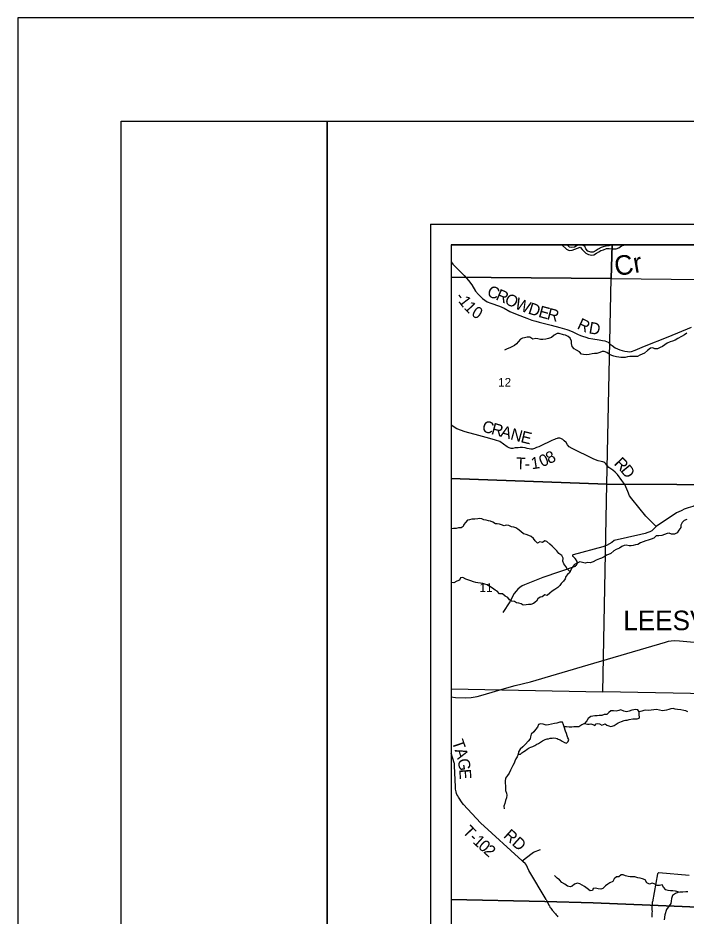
# Model space of a CAD drawing. Extents: x -7.1 to 34, y 0 to 22.
# Drawn here: x 0 to 3.24, y 17.646 to 22 of the extents above; entities that cross this region are included whole.
import ezdxf

# ---------------------------------------------------------------- set-up
doc = ezdxf.new("R2010")
doc.units = 0
for name, color, linetype in [('Default', 7, 'Continuous'), ('GM_X_Corporation_Text', 7, 'Continuous'), ('GM_X_County_Road', 7, 'Continuous'), ('GM_X_Major_River', 7, 'Continuous'), ('GM_X_Major_River_Text', 7, 'Continuous'), ('GM_X_Minor_Lake', 7, 'Continuous'), ('GM_X_Minor_River', 7, 'Continuous'), ('GM_X_Section', 7, 'Continuous'), ('GM_X_Section_Text', 7, 'Continuous'), ('GM_X_Township_Road', 7, 'Continuous'), ('GM_X_Township_Road_Text', 7, 'Continuous'), ('SH_Border', 7, 'Continuous'), ('SH_Cut_Line', 7, 'Continuous'), ('SH_Data', 7, 'Continuous')]:
    doc.layers.add(name, color=color, linetype=linetype)

msp = doc.modelspace()

# ---------------------------------------------------------------- linework, layer by layer
at = {"layer": 'Default'}
for points in [[(2.8816, 20.9), (2.1, 20.9), (2.1, 20.744), (2.8771, 20.7376)], [(3.8966, 20.9), (2.8816, 20.9), (2.8771, 20.7376), (3.8931, 20.7247), (3.8945, 20.8149)], [(2.1, 20.744), (2.1, 19.7672), (2.8549, 19.7393), (2.8771, 20.7376)], [(2.1, 19.7672), (2.1, 18.7473), (2.8366, 18.7324), (2.8549, 19.7393)]]:
    msp.add_lwpolyline(points, close=True, dxfattribs=at)
at = {"layer": 'GM_X_County_Road'}
for points in [[(2.1, 18.7082), (2.1223, 18.7056), (2.1681, 18.7043), (2.1971, 18.7058), (2.2265, 18.7097), (2.2451, 18.7146), (2.2989, 18.7315), (2.3593, 18.7497), (2.4106, 18.7642), (2.485, 18.7817), (2.7659, 18.8631), (3.1394, 18.9737), (3.1551, 18.9777), (3.1669, 18.9796), (3.1823, 18.9814), (3.2073, 18.9808), (3.3146, 18.9707)], [(2.5617, 17.7254), (2.5679, 17.7128), (2.5748, 17.6987), (2.577, 17.6944), (2.5799, 17.6895), (2.5834, 17.6843), (2.5874, 17.6787), (2.5909, 17.6743), (2.606, 17.6566), (2.6103, 17.6518), (2.6154, 17.6461), (2.6188, 17.6425)]]:
    msp.add_lwpolyline(points, dxfattribs=at)
at = {"layer": 'GM_X_Major_River'}
for points in [[(2.6372, 20.9), (2.6597, 20.8783), (2.6734, 20.8725), (2.6875, 20.8735), (2.6999, 20.8797), (2.7139, 20.8845), (2.7264, 20.8893), (2.7357, 20.8773), (2.745, 20.8672), (2.7546, 20.859), (2.7669, 20.8539), (2.7825, 20.8496), (2.7924, 20.8517), (2.8055, 20.8599), (2.8165, 20.8658), (2.8262, 20.8727), (2.8391, 20.8764), (2.8535, 20.8819), (2.8668, 20.8818), (2.8782, 20.8804), (2.8877, 20.8802), (2.9006, 20.8812), (2.9135, 20.8856), (2.927, 20.8949), (2.9383, 20.8981), (2.9491, 20.9)], [(2.8887, 20.9), (2.8771, 20.8979), (2.8646, 20.895), (2.8521, 20.8929), (2.8385, 20.89), (2.8287, 20.8872), (2.8132, 20.8797), (2.8034, 20.8724), (2.7899, 20.8645), (2.7774, 20.864), (2.7643, 20.8694), (2.7543, 20.8806), (2.7487, 20.8934), (2.7361, 20.8989), (2.7243, 20.8987), (2.7118, 20.8962), (2.699, 20.8888), (2.6861, 20.8871), (2.6739, 20.8884), (2.6627, 20.9)]]:
    msp.add_lwpolyline(points, dxfattribs=at)
at = {"layer": 'GM_X_Minor_Lake'}
for points in [[(3.012, 18.635), (3.0062, 18.6448), (2.9967, 18.647), (2.9865, 18.6454), (2.9766, 18.6434), (2.9645, 18.6387), (2.9505, 18.6352), (2.9375, 18.6393), (2.9238, 18.6456), (2.9139, 18.6428), (2.9007, 18.6397), (2.8881, 18.64), (2.8752, 18.6406), (2.8654, 18.6333), (2.8556, 18.623), (2.8423, 18.6221), (2.8317, 18.6186), (2.8188, 18.6177), (2.8086, 18.6161), (2.7979, 18.6157), (2.7884, 18.6148), (2.7782, 18.6132), (2.7654, 18.6032), (2.7594, 18.5914), (2.7477, 18.5799)], [(2.7477, 18.5799), (2.7614, 18.5755), (2.7698, 18.5767), (2.7785, 18.5779), (2.7876, 18.5749), (2.7968, 18.5697), (2.804, 18.5774), (2.8115, 18.5797), (2.8203, 18.5779), (2.831, 18.5719), (2.8393, 18.575), (2.8476, 18.577), (2.856, 18.5714), (2.8648, 18.5673), (2.8736, 18.5654), (2.8819, 18.5666), (2.8918, 18.5701), (2.9001, 18.5755), (2.9099, 18.5817), (2.919, 18.5863), (2.9269, 18.5894), (2.9394, 18.5945), (2.9455, 18.5957), (2.955, 18.5961), (2.9644, 18.5985), (2.9811, 18.6017), (2.9929, 18.6018), (3.0032, 18.6026), (3.0122, 18.6046), (3.0141, 18.6103), (3.0125, 18.6209), (3.012, 18.635)], [(2.6491, 18.5631), (2.646, 18.5733), (2.6413, 18.5858), (2.628, 18.585), (2.6133, 18.5803), (2.6011, 18.5794), (2.5875, 18.5759), (2.5731, 18.5735), (2.5617, 18.5715), (2.5465, 18.5755), (2.5347, 18.5769), (2.5244, 18.5746), (2.5188, 18.5612), (2.5094, 18.5505), (2.502, 18.5383), (2.4895, 18.528), (2.4847, 18.5142), (2.4832, 18.5044), (2.4742, 18.4933), (2.461, 18.4795), (2.4482, 18.4669), (2.4354, 18.4546), (2.4272, 18.4416), (2.4261, 18.4298)], [(2.4261, 18.4298), (2.4364, 18.4299), (2.4439, 18.4368), (2.453, 18.4434), (2.4617, 18.4484), (2.47, 18.4541), (2.4791, 18.4607), (2.4874, 18.4645), (2.4969, 18.4677), (2.5063, 18.4719), (2.5161, 18.4785), (2.5244, 18.4827), (2.5343, 18.4885), (2.5441, 18.4954), (2.5566, 18.5012), (2.5664, 18.5043), (2.5721, 18.5051), (2.5812, 18.5075), (2.5911, 18.5087), (2.5994, 18.5092), (2.6086, 18.5077), (2.6143, 18.5066), (2.6204, 18.504), (2.6288, 18.5003), (2.6398, 18.4939), (2.6501, 18.4872), (2.6604, 18.4846), (2.6679, 18.4923), (2.6709, 18.5011), (2.667, 18.5105), (2.6632, 18.5196), (2.6593, 18.5302), (2.6554, 18.5415), (2.6491, 18.5631)]]:
    msp.add_lwpolyline(points, dxfattribs=at)
at = {"layer": 'GM_X_Minor_River'}
for points in [[(3.2428, 20.4712), (3.2319, 20.4639), (3.2175, 20.4558), (3.2005, 20.4461), (3.1877, 20.4384), (3.1733, 20.4326), (3.1623, 20.4299), (3.1487, 20.4225), (3.1373, 20.4149), (3.1249, 20.4068), (3.115, 20.4025), (3.1018, 20.396), (3.0881, 20.3955), (3.0786, 20.4014), (3.0668, 20.3995), (3.0525, 20.3876), (3.0382, 20.3749), (3.0276, 20.3703), (3.0162, 20.3645), (3.0041, 20.3591), (2.9897, 20.3582), (2.9802, 20.3589), (2.9677, 20.358), (2.9552, 20.3568), (2.9438, 20.3544), (2.9328, 20.3531), (2.9233, 20.3534), (2.9138, 20.3549), (2.9027, 20.3571), (2.8898, 20.36), (2.8795, 20.3629), (2.8662, 20.3704), (2.8551, 20.3783), (2.8433, 20.3835), (2.833, 20.3826), (2.8224, 20.3772), (2.8065, 20.3725), (2.7951, 20.3732), (2.7852, 20.3723), (2.7701, 20.3684), (2.7568, 20.3675), (2.7427, 20.3689), (2.7332, 20.3704), (2.7225, 20.3817), (2.7091, 20.3891), (2.698, 20.3962), (2.6869, 20.4075), (2.6838, 20.4223), (2.6848, 20.4333), (2.6778, 20.4469), (2.6679, 20.4555), (2.6545, 20.4623), (2.645, 20.4629), (2.6252, 20.4696), (2.615, 20.4699), (2.5995, 20.4622), (2.5867, 20.4507), (2.5726, 20.4452), (2.5598, 20.4421), (2.5453, 20.4412), (2.5332, 20.4407), (2.5206, 20.444), (2.5111, 20.4455), (2.4963, 20.4431), (2.4826, 20.452), (2.4696, 20.4523), (2.4564, 20.4488)], [(2.4564, 20.4488), (2.4469, 20.4479), (2.4371, 20.4429), (2.425, 20.4299), (2.4183, 20.42), (2.4081, 20.4119), (2.3983, 20.4069), (2.3854, 20.4011), (2.3725, 20.3964), (2.3601, 20.3891)], [(2.6777, 19.3143), (2.663, 19.3295), (2.6565, 19.3408), (2.6469, 19.354), (2.6429, 19.3669), (2.6436, 19.3802), (2.6374, 19.3938), (2.6232, 19.4039), (2.6129, 19.416), (2.5999, 19.4291), (2.5899, 19.4397), (2.5788, 19.4494), (2.5654, 19.4611), (2.5555, 19.4655), (2.5442, 19.4575), (2.5312, 19.46), (2.5195, 19.4535), (2.5088, 19.4651), (2.5007, 19.4764), (2.4884, 19.4858), (2.477, 19.491), (2.4637, 19.4959), (2.4519, 19.4992), (2.4392, 19.5097), (2.4247, 19.5213), (2.4148, 19.5284), (2.4052, 19.5318), (2.3931, 19.5332), (2.3805, 19.5395), (2.3679, 19.5406), (2.3573, 19.5374), (2.3444, 19.5426), (2.3345, 19.5452), (2.3246, 19.5474), (2.3151, 19.5481), (2.3021, 19.5555), (2.2914, 19.5608), (2.2815, 19.5618), (2.2697, 19.5647), (2.2598, 19.5669), (2.2488, 19.571), (2.2389, 19.5724), (2.2294, 19.5712), (2.215, 19.57), (2.2009, 19.5695), (2.1899, 19.5675), (2.1801, 19.5651), (2.1703, 19.5544), (2.1628, 19.5445), (2.1587, 19.5346), (2.1485, 19.5276), (2.1371, 19.5272), (2.1242, 19.5244), (2.1121, 19.5251), (2.1, 19.5223)], [(3.244, 19.5682), (3.2311, 19.5636), (3.2205, 19.554), (3.2142, 19.5411), (3.2139, 19.5289), (3.2049, 19.5171), (3.1959, 19.5033), (3.1834, 19.4979), (3.1698, 19.4974), (3.1579, 19.5015), (3.1485, 19.4999), (3.1356, 19.4952), (3.1227, 19.4902), (3.1079, 19.4885), (3.0946, 19.4884), (3.0833, 19.4781), (3.0708, 19.4727), (3.0561, 19.4687), (3.0443, 19.4648), (3.0326, 19.4598), (3.0193, 19.4551), (3.0053, 19.4474), (2.9944, 19.4451), (2.9841, 19.4419), (2.9739, 19.4407), (2.9632, 19.441), (2.9499, 19.4432), (2.9389, 19.4415), (2.9276, 19.4376), (2.9166, 19.4296), (2.9015, 19.4234), (2.889, 19.4164), (2.8754, 19.4042), (2.8637, 19.3988), (2.8539, 19.3957), (2.8422, 19.388), (2.8293, 19.3806)], [(2.8293, 19.3806), (2.8195, 19.3771), (2.8032, 19.3713), (2.7892, 19.3625), (2.7741, 19.3582), (2.7619, 19.3603), (2.7498, 19.3568), (2.7383, 19.3601), (2.7246, 19.3623), (2.7122, 19.3572), (2.6985, 19.3495), (2.688, 19.335), (2.6802, 19.3209), (2.6765, 19.311), (2.6648, 19.3014), (2.6565, 19.2919), (2.6532, 19.2801), (2.6461, 19.2686), (2.6344, 19.2587), (2.6284, 19.2484), (2.6175, 19.238), (2.6039, 19.2292), (2.5907, 19.2204), (2.579, 19.2111), (2.5669, 19.2004), (2.5543, 19.2037), (2.5419, 19.1926), (2.532, 19.1925), (2.5215, 19.1829), (2.514, 19.173), (2.5004, 19.1615), (2.4871, 19.1568), (2.4765, 19.1556), (2.464, 19.154), (2.4503, 19.1527), (2.4408, 19.1595), (2.4294, 19.1632), (2.4172, 19.165), (2.4073, 19.1702), (2.3939, 19.1731), (2.3844, 19.1795), (2.3752, 19.1896), (2.3626, 19.196), (2.35, 19.2073), (2.3359, 19.2087), (2.3244, 19.2203), (2.3137, 19.2252), (2.3011, 19.2357), (2.2878, 19.2428), (2.2751, 19.2514), (2.2645, 19.2551), (2.2549, 19.2584), (2.2428, 19.2602), (2.2298, 19.262), (2.2196, 19.2634), (2.2085, 19.2664), (2.196, 19.2716), (2.1857, 19.2745), (2.1716, 19.2793), (2.1578, 19.2876), (2.1465, 19.2852), (2.1405, 19.2734), (2.1276, 19.2695), (2.1136, 19.2606), (2.1007, 19.2624), (2.1, 19.2627)], [(3.2479, 18.6355), (3.2383, 18.6403), (3.2284, 18.6425), (3.214, 18.6447), (3.1988, 18.6476), (3.187, 18.6494), (3.1771, 18.6516), (3.1664, 18.6499), (3.1566, 18.6476), (3.1448, 18.6441), (3.1354, 18.6421), (3.1251, 18.6412), (3.1114, 18.6442), (3.0966, 18.6471), (3.0833, 18.6462), (3.07, 18.6442), (3.0571, 18.6429), (3.045, 18.644), (3.0351, 18.6416), (3.0253, 18.6385), (3.012, 18.635), (3.0062, 18.6448), (2.9967, 18.647), (2.9865, 18.6454), (2.9766, 18.6434), (2.9645, 18.6387), (2.9505, 18.6352), (2.9375, 18.6393), (2.9238, 18.6456), (2.9139, 18.6428), (2.9007, 18.6397), (2.8881, 18.64), (2.8752, 18.6406), (2.8654, 18.6333), (2.8556, 18.623), (2.8423, 18.6221), (2.8317, 18.6186), (2.8188, 18.6177), (2.8086, 18.6161), (2.7979, 18.6157), (2.7884, 18.6148), (2.7782, 18.6132), (2.7654, 18.6032), (2.7594, 18.5914), (2.7477, 18.5799), (2.7349, 18.5722), (2.7194, 18.5633), (2.6962, 18.5631), (2.6867, 18.5608), (2.6734, 18.5607), (2.6605, 18.5632), (2.6491, 18.5631), (2.646, 18.5733), (2.6413, 18.5858), (2.628, 18.585), (2.6133, 18.5803), (2.6011, 18.5794), (2.5875, 18.5759), (2.5731, 18.5735), (2.5617, 18.5715), (2.5465, 18.5755), (2.5347, 18.5769), (2.5244, 18.5746), (2.5188, 18.5612), (2.5094, 18.5505), (2.502, 18.5383), (2.4895, 18.528), (2.4847, 18.5142), (2.4832, 18.5044), (2.4742, 18.4933), (2.461, 18.4795), (2.4482, 18.4669), (2.4354, 18.4546), (2.4272, 18.4416), (2.4261, 18.4298), (2.4202, 18.4169), (2.4146, 18.4073), (2.4101, 18.397), (2.406, 18.3875), (2.3992, 18.3761), (2.3952, 18.3658), (2.388, 18.3524), (2.3817, 18.3391), (2.3734, 18.3276), (2.3644, 18.3139), (2.3623, 18.2998), (2.3624, 18.2899), (2.364, 18.2771), (2.3648, 18.266), (2.3649, 18.255), (2.3685, 18.2418), (2.3704, 18.2319), (2.369, 18.219), (2.3646, 18.2064), (2.3617, 18.1912)], [(2.3617, 18.1912), (2.3568, 18.1783), (2.3581, 18.1661)], [(3.2059, 17.7611), (3.1883, 17.7663), (3.1758, 17.7673), (3.1648, 17.7684), (3.1526, 17.7698), (3.1423, 17.7727), (3.1312, 17.7859), (3.1239, 17.7969), (3.1114, 17.7945), (3.0996, 17.794), (3.0858, 17.8019), (3.0759, 17.8044), (3.0623, 17.8001), (3.049, 17.8072), (3.0409, 17.8208), (3.0283, 17.8264), (3.0169, 17.8294), (3.0055, 17.8312), (2.9917, 17.8363), (2.9686, 17.8361), (2.9583, 17.8376), (2.9457, 17.8413), (2.9354, 17.8457), (2.9259, 17.846), (2.9135, 17.8364), (2.9032, 17.8356), (2.8912, 17.8267), (2.8844, 17.8138), (2.8704, 17.8061), (2.8599, 17.8007), (2.8485, 17.7918), (2.8365, 17.7788), (2.827, 17.7768), (2.8129, 17.7782), (2.8, 17.7808), (2.7886, 17.7795), (2.786, 17.7689), (2.7743, 17.768), (2.7601, 17.7789), (2.7468, 17.7883), (2.7368, 17.7954), (2.725, 17.8021), (2.7128, 17.8054), (2.6988, 17.8), (2.6883, 17.7908), (2.6784, 17.7869), (2.6647, 17.7898), (2.6517, 17.7996), (2.6372, 17.8078), (2.6253, 17.8214), (2.615, 17.8297), (2.6012, 17.8421)], [(3.2487, 17.763), (3.2389, 17.7626), (3.2241, 17.7621), (3.2115, 17.7619), (3.2001, 17.7603), (3.1892, 17.7553), (3.1748, 17.7449), (3.1696, 17.7308), (3.1682, 17.7179), (3.1664, 17.7061), (3.1583, 17.6945)], [(3.1583, 17.6945), (3.145, 17.677), (3.1367, 17.6509), (3.1335, 17.627)]]:
    msp.add_lwpolyline(points, dxfattribs=at)
at = {"layer": 'GM_X_Section'}
for points in [[(3.8931, 20.7247), (3.8731, 19.8315), (3.8749, 19.7341), (2.8549, 19.7393), (2.8771, 20.7376)], [(2.8549, 19.7393), (3.8749, 19.7341), (3.8597, 18.828), (3.8583, 18.7127), (2.8366, 18.7324)]]:
    msp.add_lwpolyline(points, close=True, dxfattribs=at)
at = {"layer": 'GM_X_Township_Road'}
for points in [[(6.7921, 20.9), (2.1, 20.9), (2.1, 17.7253), (2.5551, 17.7155), (2.7886, 17.7105), (3.0659, 17.6986), (3.7215, 17.6707)], [(2.1, 20.8178), (2.1093, 20.8061), (2.1276, 20.7866), (2.1631, 20.7517), (2.1852, 20.7267), (2.2007, 20.706), (2.2193, 20.6752), (2.2326, 20.659), (2.2461, 20.6456), (2.2523, 20.6392), (2.2634, 20.6313), (2.2757, 20.6244), (2.293, 20.6171), (2.3358, 20.602), (2.357, 20.5924), (2.3855, 20.5776), (2.4211, 20.5616), (2.467, 20.5449), (2.4924, 20.5355), (2.5115, 20.5303), (2.5274, 20.5253), (2.5853, 20.5099), (2.6281, 20.4987), (2.6617, 20.4898), (2.6708, 20.4863), (2.6913, 20.4785), (2.7141, 20.4674), (2.7273, 20.4612), (2.7371, 20.4568), (2.7533, 20.4516), (2.7675, 20.448), (2.7877, 20.4439), (2.8181, 20.44), (2.8349, 20.4367), (2.8454, 20.4339), (2.8534, 20.4311), (2.8615, 20.4274), (2.8725, 20.4192), (2.8814, 20.4124), (2.8963, 20.4011), (2.9072, 20.395), (2.919, 20.3908), (2.9295, 20.3885), (2.9435, 20.385), (2.9553, 20.3828), (2.9665, 20.382), (2.9755, 20.3834), (2.9923, 20.389), (3.0375, 20.4082), (3.1531, 20.4542), (3.266, 20.5001)], [(3.0953, 19.5347), (3.0442, 19.5847), (2.9763, 19.6678), (2.9661, 19.6836), (2.9568, 19.7045), (2.9434, 19.738), (2.9287, 19.7572), (2.9068, 19.7865), (2.8967, 19.7971), (2.8841, 19.8074), (2.8651, 19.8207), (2.8565, 19.8296), (2.8503, 19.8377), (2.8467, 19.8426), (2.8417, 19.8468), (2.8368, 19.8486), (2.8274, 19.8498), (2.8139, 19.8525), (2.8011, 19.8574), (2.7898, 19.8631), (2.6882, 19.9126), (2.6728, 19.9214), (2.6653, 19.9297), (2.6587, 19.941), (2.6494, 19.9504), (2.6418, 19.9561), (2.6323, 19.9606), (2.6278, 19.962), (2.6232, 19.9625), (2.6185, 19.9622), (2.6149, 19.9611), (2.6086, 19.9589), (2.6017, 19.9567), (2.5972, 19.9548), (2.5885, 19.9511), (2.5728, 19.9438), (2.5478, 19.9314), (2.5264, 19.9212), (2.5149, 19.9172), (2.5048, 19.9133), (2.4954, 19.91), (2.4911, 19.909), (2.4875, 19.9093), (2.4791, 19.9107), (2.4694, 19.9126), (2.4594, 19.9151), (2.4472, 19.9172), (2.4354, 19.9166), (2.4253, 19.9161), (2.4115, 19.9153), (2.3991, 19.9131), (2.3923, 19.9127), (2.3827, 19.9151), (2.3718, 19.9212), (2.3548, 19.9343), (2.3363, 19.9467), (2.3164, 19.9536), (2.2879, 19.9611), (2.2356, 19.976), (2.1686, 19.9928), (2.1289, 20.0086), (2.1, 20.0261)], [(3.478, 19.7411), (3.4677, 19.7405), (3.4499, 19.7412), (3.4327, 19.7409), (3.4218, 19.7399), (3.4145, 19.7372), (3.4066, 19.7309), (3.3985, 19.7259), (3.3893, 19.718), (3.3841, 19.7101), (3.3775, 19.7016), (3.3719, 19.6926), (3.3595, 19.6782), (3.3571, 19.6743), (3.3544, 19.6714), (3.3489, 19.6673), (3.3257, 19.6553), (3.2732, 19.6316), (3.2504, 19.6251), (3.2304, 19.6186), (3.2191, 19.6117), (3.2154, 19.6102), (3.1942, 19.6014), (3.0953, 19.5347)], [(3.0953, 19.5347), (3.0799, 19.5193), (3.0739, 19.5136), (3.0646, 19.5085), (3.0539, 19.5052), (3.0414, 19.501), (3.0209, 19.495), (2.8918, 19.4662), (2.8797, 19.4576), (2.8542, 19.4425), (2.837, 19.4365), (2.6929, 19.3969), (2.6912, 19.3962), (2.6905, 19.3958), (2.6899, 19.395), (2.6894, 19.394), (2.6893, 19.3924), (2.6897, 19.3912), (2.6908, 19.39), (2.6985, 19.3826), (2.6997, 19.3811)], [(2.6997, 19.3811), (2.7009, 19.3796), (2.7024, 19.3771), (2.7095, 19.3649), (2.7106, 19.3618), (2.7115, 19.3581), (2.711, 19.3542), (2.709, 19.3493), (2.7069, 19.3457), (2.7045, 19.343), (2.7019, 19.3412), (2.5455, 19.2876), (2.4563, 19.2515), (2.4453, 19.2463), (2.4344, 19.2388), (2.4243, 19.2302), (2.4162, 19.2215), (2.4067, 19.2092), (2.3849, 19.1692), (2.3518, 19.1174)], [(2.5617, 17.7254), (2.4768, 17.8671), (2.4712, 17.8811), (2.4656, 17.8924), (2.4617, 17.8987), (2.4601, 17.9006), (2.4505, 17.9093), (2.4456, 17.9137), (2.2438, 18.0973), (2.1607, 18.1867), (2.1547, 18.1944), (2.1365, 18.2216), (2.1323, 18.2283), (2.1285, 18.2352), (2.1269, 18.2398), (2.1246, 18.248), (2.1221, 18.2606), (2.1211, 18.2723), (2.1167, 18.3737), (2.1165, 18.3854), (2.1161, 18.3886), (2.1089, 18.4097), (2.1, 18.4347)], [(2.4456, 17.9137), (2.4935, 17.9512), (2.4999, 17.9549), (2.5344, 17.9685)], [(3.2545, 17.8421), (3.1086, 17.855), (3.1067, 17.8546), (3.1045, 17.854), (3.1026, 17.8527), (3.1015, 17.851), (3.0763, 17.7146)], [(6.7058, 17.2839), (6.7118, 17.7486), (6.3575, 17.7557), (6.1904, 17.7592), (5.7514, 17.7685), (5.5047, 17.7737), (5.1115, 17.7819), (5.0544, 17.7831), (5.0443, 17.7832), (4.7094, 17.7848), (4.5657, 17.7857), (4.3, 17.7873), (3.8304, 17.7952), (3.8238, 17.6717), (3.7215, 17.6707), (3.0659, 17.6986), (2.7886, 17.7105), (2.5551, 17.7155), (2.1, 17.7253), (2.1, 14.1)], [(3.0751, 17.6409), (3.0759, 17.6531), (3.0762, 17.661), (3.0764, 17.6685), (3.0762, 17.6756), (3.0759, 17.6876), (3.0763, 17.7146)]]:
    msp.add_lwpolyline(points, dxfattribs=at)
at = {"layer": 'SH_Border'}
for points in [[(0.5, 21.5), (1.5, 21.5), (1.5, 0.5), (0.5, 0.5)], [(1.5, 21.5), (33.5, 21.5), (33.5, 0.5), (1.5, 0.5)]]:
    msp.add_lwpolyline(points, close=True, dxfattribs=at)
at = {"layer": 'SH_Cut_Line'}
for points in [[(0, 0), (34, 0), (34, 22), (0, 22)], [(8.9, 17.7079), (8.9, 20.9), (2.1, 20.9), (2.1, 17.7253), (2.5551, 17.7155), (2.7886, 17.7105), (3.0659, 17.6986), (3.7215, 17.6707), (3.8238, 17.6717), (3.8304, 17.7952), (4.3, 17.7873), (4.5657, 17.7857), (4.7094, 17.7848), (5.0443, 17.7832), (5.0544, 17.7831), (5.1115, 17.7819), (5.5047, 17.7737), (5.7514, 17.7685), (6.1904, 17.7592), (6.3575, 17.7557), (6.7118, 17.7486), (7.7202, 17.7285), (8.4472, 17.7189), (8.6668, 17.7136)], [(2.1, 17.7253), (2.1, 14.1), (8.9, 14.1), (8.9, 17.7079), (8.6668, 17.7136), (8.4472, 17.7189), (7.7202, 17.7285), (6.7118, 17.7486), (6.3575, 17.7557), (6.1904, 17.7592), (5.7514, 17.7685), (5.5047, 17.7737), (5.1115, 17.7819), (5.0544, 17.7831), (5.0443, 17.7832), (4.7094, 17.7848), (4.5657, 17.7857), (4.3, 17.7873), (3.8304, 17.7952), (3.8238, 17.6717), (3.7215, 17.6707), (3.0659, 17.6986), (2.7886, 17.7105), (2.5551, 17.7155)]]:
    msp.add_lwpolyline(points, close=True, dxfattribs=at)
at = {"layer": 'SH_Data'}
for p, q in [((2, 21), (9, 21)), ((2, 21), (2, 14)), ((2.1, 20.9), (2.1, 14.1)), ((2.1, 20.9), (8.9, 20.9))]:
    msp.add_line(p, q, dxfattribs=at)

# ---------------------------------------------------------------- texts
at = {"layer": 'GM_X_Corporation_Text'}
msp.add_text('LEESVILLE', height=0.0947, rotation=0, dxfattribs=at).set_placement((2.9353, 19.0317))
at = {"layer": 'GM_X_Major_River_Text'}
msp.add_text('Cr', height=0.09471, rotation=9.5544, dxfattribs=at).set_placement((2.9003, 20.7478))
at = {"layer": 'GM_X_Section_Text'}
for s, p in [('12', (2.329, 20.2127)), ('11', (2.2386, 19.2174))]:
    msp.add_text(s, height=0.04186, rotation=0, dxfattribs=at).set_placement(p)
at = {"layer": 'GM_X_Township_Road_Text'}
for s, height, rotation, p in [('C', 0.0568, 337.4108, (2.2705, 20.6539)), ('R', 0.0568, 336.6474, (2.3134, 20.636)), ('-', 0.0568, 304.8825, (2.1183, 20.6478)), ('1', 0.0568, 307.6149, (2.1334, 20.6263)), ('O', 0.0568, 333.2191, (2.3554, 20.6179)), ('W', 0.0568, 338.5253, (2.4053, 20.593)), ('1', 0.0568, 314.1011, (2.1594, 20.5933)), ('0', 0.0568, 327.6955, (2.1951, 20.5589)), ('D', 0.0568, 342.2379, (2.4704, 20.5676)), ('E', 0.0568, 344.8007, (2.5206, 20.5515)), ('R', 0.0568, 345.0105, (2.5619, 20.5403)), ('R', 0.0568, 335.172, (2.7078, 20.4957)), ('D', 0.0568, 350.0658, (2.7652, 20.4714)), ('C', 0.0568, 345.0081, (2.2464, 19.9955)), ('R', 0.0568, 344.5953, (2.2914, 19.9834)), ('A', 0.0568, 344.5938, (2.3364, 19.971)), ('N', 0.0568, 344.6417, (2.3847, 19.9577)), ('E', 0.0568, 346.3372, (2.4346, 19.944)), ('8', 0.0568, 25.5761, (2.5757, 19.8361)), ('T', 0.0568, 357.9639, (2.4142, 19.813)), ('1', 0.0568, 8.7869, (2.4917, 19.8114)), ('0', 0.0568, 23.5354, (2.5416, 19.8212)), ('R', 0.0568, 314.5915, (2.8873, 19.8369)), ('-', 0.0568, 358.0748, (2.4568, 19.8115)), ('D', 0.0568, 309.2774, (2.9192, 19.8047)), ('T', 0.0568, 289.1011, (2.1035, 18.4904)), ('A', 0.0568, 287.4097, (2.1173, 18.4506)), ('G', 0.0568, 279.2159, (2.1317, 18.405)), ('E', 0.0568, 273.3511, (2.1396, 18.3572)), ('T', 0.0568, 314.0469, (2.1524, 18.0519)), ('-', 0.0568, 317.0684, (2.1843, 18.0191)), ('1', 0.0568, 317.6344, (2.2018, 18.0027)), ('RD', 0.05682, 317.7918, (2.3511, 18.0306)), ('0', 0.0568, 317.9517, (2.2279, 17.9789)), ('2', 0.0568, 318.0315, (2.254, 17.9554))]:
    msp.add_text(s, height=height, rotation=rotation, dxfattribs=at).set_placement(p)

doc.saveas('drawing.dxf')
